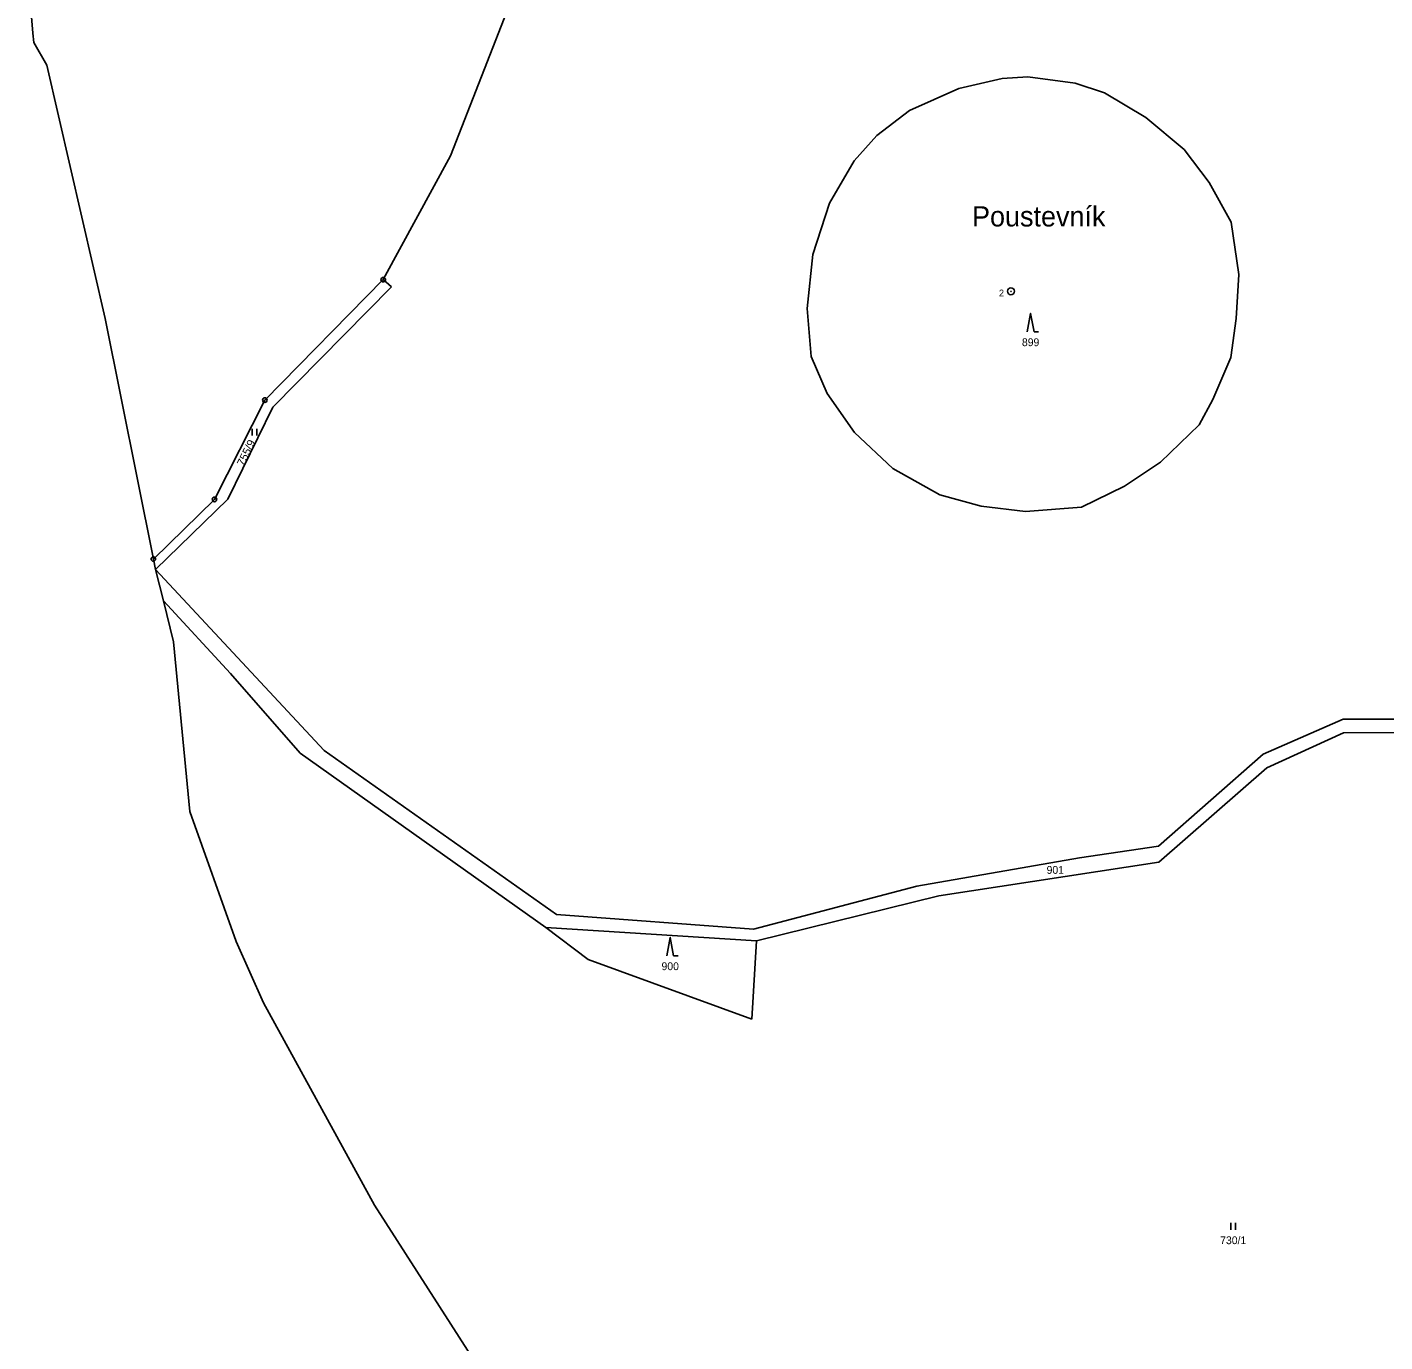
# Model space of a CAD drawing. Extents: x -739410 to -735662, y -942282 to -940043.
# Drawn here: x -738387.3 to -738091.3, y -940907.3 to -940620.7 of the extents above; entities that cross this region are included whole.
import ezdxf
from ezdxf.enums import TextEntityAlignment as Align

# ---------------------------------------------------------------- set-up
doc = ezdxf.new("R2010")
doc.units = 0
doc.header["$LTSCALE"] = 0.68
for name, color, linetype, lineweight in [('1', 7, 'Continuous', 25), ('3', 7, 'Continuous', 25), ('7', 7, 'Continuous', 13), ('8', 7, 'Continuous', 25)]:
    doc.layers.add(name, color=color, linetype=linetype, lineweight=lineweight)
doc.layers.add('2', color=7, linetype='Continuous')

msp = doc.modelspace()

# ---------------------------------------------------------------- linework, layer by layer
at = {"layer": '1'}
for p, q in [((-738295.01, -940648.74), (-738275.92, -940599.66)), ((-738387.35, -940607.29), (-738386.08, -940622.05)), ((-738386.08, -940622.05), (-738385.91, -940624.03)), ((-738385.91, -940624.03), (-738383.08, -940629)), ((-738383.08, -940629), (-738370.31, -940684.24)), ((-738184.17, -940634.09), (-738174.74, -940631.92)), ((-738174.74, -940631.92), (-738169.12, -940631.51)), ((-738169.12, -940631.51), (-738158.81, -940632.9)), ((-738158.81, -940632.9), (-738152.4, -940635.06)), ((-738194.91, -940638.85), (-738184.17, -940634.09)), ((-738152.4, -940635.06), (-738143.4, -940640.43)), ((-738202.1, -940644.31), (-738194.91, -940638.85)), ((-738143.4, -940640.43), (-738135.08, -940647.36)), ((-738207.03, -940649.85), (-738202.1, -940644.31)), ((-738309.7, -940675.76), (-738295.01, -940648.74)), ((-738135.08, -940647.36), (-738129.63, -940654.55)), ((-738212.4, -940659.1), (-738207.03, -940649.85)), ((-738129.63, -940654.55), (-738124.78, -940663.21)), ((-738216.03, -940670.27), (-738212.4, -940659.1)), ((-738124.78, -940663.21), (-738123.16, -940674.61)), ((-738217.24, -940682.05), (-738216.03, -940670.27)), ((-738123.16, -940674.61), (-738123.68, -940684.22)), ((-738335.51, -940702.01), (-738309.7, -940675.76)), ((-738333.77, -940703.58), (-738307.91, -940677.33)), ((-738309.7, -940675.76), (-738307.91, -940677.33)), ((-738370.31, -940684.24), (-738359.83, -940736.66)), ((-738216.38, -940692.53), (-738217.24, -940682.05)), ((-738123.68, -940684.22), (-738124.89, -940692.71)), ((-738212.91, -940700.59), (-738216.38, -940692.53)), ((-738124.89, -940692.71), (-738128.78, -940701.89)), ((-738346.5, -940723.66), (-738335.51, -940702.01)), ((-738206.94, -940709.07), (-738212.91, -940700.59)), ((-738128.78, -940701.89), (-738131.81, -940707.44)), ((-738333.77, -940703.58), (-738343.62, -940723.59)), ((-738131.81, -940707.44), (-738140.2, -940715.55)), ((-738198.54, -940716.96), (-738206.94, -940709.07)), ((-738140.2, -940715.55), (-738148.08, -940720.75)), ((-738188.35, -940722.66), (-738198.54, -940716.96)), ((-738179.34, -940725.17), (-738188.35, -940722.66)), ((-738148.08, -940720.75), (-738157.44, -940725.34)), ((-738359.83, -940736.66), (-738346.5, -940723.66)), ((-738343.62, -940723.59), (-738359.34, -940738.93)), ((-738169.65, -940726.29), (-738179.34, -940725.17)), ((-738157.44, -940725.34), (-738169.65, -940726.29)), ((-738359.83, -940736.66), (-738359.34, -940738.93)), ((-738359.34, -940738.93), (-738357.65, -940745.78)), ((-738359.34, -940738.93), (-738322.59, -940778.38)), ((-738357.65, -940745.78), (-738355.44, -940754.71)), ((-738357.65, -940745.78), (-738343.03, -940761.65)), ((-738355.44, -940754.71), (-738351.85, -940791.74)), ((-738343.03, -940761.65), (-738327.79, -940778.97)), ((-738117.84, -940779.21), (-738100.35, -940771.59)), ((-738100.35, -940771.59), (-738039.58, -940771.51)), ((-738117.01, -940782.17), (-738100.3, -940774.55)), ((-738100.3, -940774.55), (-738036.32, -940774.29)), ((-738327.79, -940778.97), (-738274.25, -940817.03)), ((-738322.59, -940778.38), (-738271.9, -940814.16)), ((-738140.65, -940799.28), (-738117.84, -940779.21)), ((-738140.6, -940802.75), (-738117.01, -940782.17)), ((-738351.85, -940791.74), (-738341.79, -940820.08)), ((-738157.88, -940801.79), (-738140.65, -940799.28)), ((-738193.37, -940808.02), (-738157.88, -940801.79)), ((-738188.55, -940810.11), (-738140.6, -940802.75)), ((-738228.97, -940817.36), (-738193.37, -940808.02)), ((-738228.32, -940819.89), (-738188.55, -940810.11)), ((-738271.9, -940814.16), (-738228.97, -940817.36)), ((-738274.25, -940817.03), (-738265.03, -940824.01)), ((-738274.25, -940817.03), (-738228.32, -940819.89)), ((-738341.79, -940820.08), (-738335.84, -940833.43)), ((-738229.3, -940836.99), (-738228.32, -940819.89)), ((-738265.03, -940824.01), (-738229.3, -940836.99)), ((-738335.84, -940833.43), (-738311.64, -940877.51)), ((-738311.64, -940877.51), (-738255.65, -940964.68))]:
    msp.add_line(p, q, dxfattribs=at)
at = {"layer": '3'}
for p, q in [((-738167.78, -940687.13), (-738166.784, -940687.13)), ((-738338.291, -940709.76), (-738338.291, -940708.26)), ((-738337.29, -940709.76), (-738337.29, -940708.26)), ((-738246.37, -940823.17), (-738245.374, -940823.17)), ((-738124.861, -940882.91), (-738124.861, -940881.41)), ((-738123.86, -940882.91), (-738123.86, -940881.41))]:
    msp.add_line(p, q, dxfattribs=at)
for points in [[(-738167.78, -940687.13), (-738168.53, -940683.13), (-738169.28, -940687.13)], [(-738246.37, -940823.17), (-738247.12, -940819.17), (-738247.87, -940823.17)]]:
    msp.add_lwpolyline(points, dxfattribs=at)
at = {"layer": '8'}
for centre, radius in [((-738309.7, -940675.7599), 0.5), ((-738309.7, -940675.7599), 0.0303), ((-738172.82, -940678.2998), 0.75), ((-738172.82, -940678.2998), 0.03), ((-738335.51, -940702.0099), 0.5), ((-738335.51, -940702.0099), 0.0303), ((-738346.5, -940723.6599), 0.5), ((-738346.5, -940723.6599), 0.0303), ((-738359.83, -940736.6599), 0.5), ((-738359.83, -940736.6599), 0.0303)]:
    msp.add_circle(centre, radius, dxfattribs=at)

# ---------------------------------------------------------------- texts
at = {"layer": '2'}
for s, p in [('899', (-738168.529, -940690.255)), ('901', (-738163.149, -940805.295)), ('900', (-738247.119, -940826.295)), ('730/1', (-738124.35, -940886.035))]:
    msp.add_text(s, height=1.7, dxfattribs=at).set_placement(p, align=Align.CENTER)
at = {"layer": '2', "width": 1.05}
msp.add_text('755/9', height=1.7, rotation=64, dxfattribs=at).set_placement((-738338.8554, -940713.8666), align=Align.CENTER)
at = {"layer": '7'}
msp.add_text('Poustevník', height=4.4, dxfattribs=at).set_placement((-738181.31, -940664.16))
at = {"layer": '8'}
msp.add_text('2', height=1.5, dxfattribs=at).set_placement((-738174.32, -940679.417), align=Align.RIGHT)

doc.saveas('drawing.dxf')
